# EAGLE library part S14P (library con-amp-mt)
AMP MT CONNECTOR
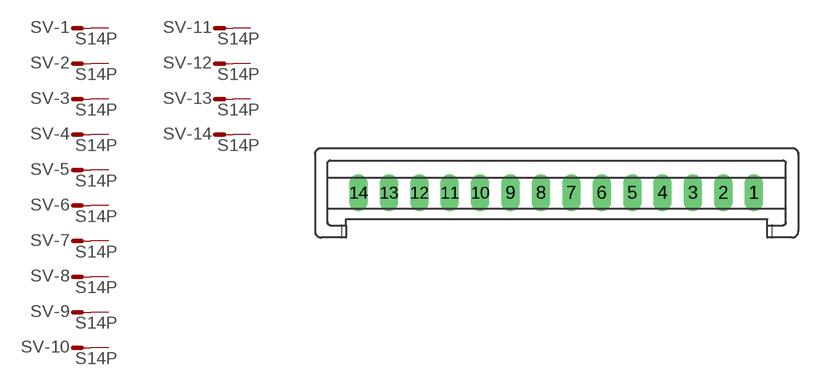
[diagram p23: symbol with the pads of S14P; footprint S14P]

Designator prefix SV; gates -1=M -2=M -3=M -4=M -5=M -6=M -7=M -8=M -9=M -10=M -11=M -12=M -13=M -14=M

## S14P (OC_FARNELL: unknown; OC_NEWARK: unknown)  [S14P]
1  -1:S  pas
2  -2:S  pas
3  -3:S  pas
4  -4:S  pas
5  -5:S  pas
6  -6:S  pas
7  -7:S  pas
8  -8:S  pas
9  -9:S  pas
10  -10:S  pas
11  -11:S  pas
12  -12:S  pas
13  -13:S  pas
14  -14:S  pas

## Footprint S14P (pad centres in mm)
AMP MT CONNECTOR
drill 1.016 long: 1 16.25,0; 2 13.75,0; 3 11.25,0; 4 8.75,0; 5 6.25,0; 6 3.75,0; 7 1.25,0; 8 -1.25,0; 9 -3.75,0; 10 -6.25,0; 11 -8.75,0; 12 -11.25,0; 13 -13.75,0; 14 -16.25,0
